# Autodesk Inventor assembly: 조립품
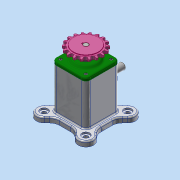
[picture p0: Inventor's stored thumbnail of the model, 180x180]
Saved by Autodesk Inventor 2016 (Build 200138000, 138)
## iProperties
Created: 2019-11
Part Number: 조립품
Material: 일반
Document SubType Name: Assembly
Designer: user
Author: user
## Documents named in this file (11)
- C:\Users\user\Desktop\491109V1008\조립품.iam
- C:\Users\user\Desktop\491109V1008\베어링 6203.ipt
- C:\Users\user\Desktop\491109V1008\본체.ipt
- C:\Users\user\Desktop\491109V1008\볼트 M4.ipt
- C:\Users\user\Desktop\491109V1008\부시.ipt
- C:\Users\user\Desktop\491109V1008\스프로킷.ipt
- C:\Users\user\Desktop\491109V1008\슬라이더.ipt
- C:\Users\user\Desktop\491109V1008\오일 실.ipt
- C:\Users\user\Desktop\491109V1008\커버.ipt
- C:\Users\user\Desktop\491109V1008\키 4 x 4 x 14.ipt
- C:\Users\user\Desktop\491109V1008\편심축.ipt
